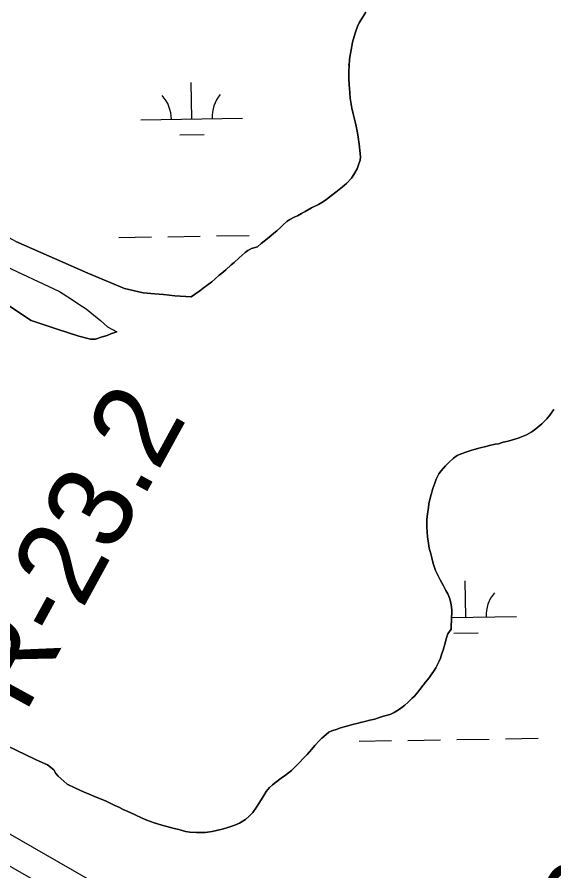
# Model space of a CAD drawing. Extents: x 3855477 to 3893699, y 299188 to 325115.
# Drawn here: x 3865378 to 3865905, y 315377 to 316217 of the extents above; entities that cross this region are included whole.
import ezdxf

# ---------------------------------------------------------------- set-up
doc = ezdxf.new("R2010")
doc.units = 0
for name, color, linetype in [('V-LEVE-TOET', 7, 'Continuous'), ('V-RIVR-EDGE', 7, 'Continuous'), ('V-RIVR-RANG-IDEN', 7, 'Continuous'), ('V-TOPO-SHOR', 7, 'Continuous'), ('V-WETL-SWMP', 7, 'Continuous')]:
    doc.layers.add(name, color=color, linetype=linetype)

msp = doc.modelspace()

# ---------------------------------------------------------------- linework, layer by layer
at = {"layer": 'V-LEVE-TOET'}
for points in [[(3865456.23, 315363.76), (3865368.76, 315414.02)], [(3865353.01, 315391.49), (3865428.99, 315348.11)]]:
    msp.add_lwpolyline(points, dxfattribs=at)
at = {"layer": 'V-RIVR-EDGE'}
msp.add_spline([(3862579.14, 316706.58), (3862618.94, 316682.57), (3862652.77, 316666.14), (3862683.04, 316656.5), (3862696.18, 316652.88), (3862701.35, 316646.89), (3862715.28, 316640.08), (3862730.01, 316634.47), (3862738.78, 316633.65), (3862748.32, 316626.05), (3862763.45, 316620.43), (3862771.01, 316614.84), (3862792.51, 316606.02), (3862806.84, 316598.81), (3862817.99, 316594.4), (3862834.31, 316586.78), (3862853.02, 316578.37), (3862861.77, 316570.77), (3862880.08, 316564.75), (3862890.05, 316564.73), (3862900.01, 316564.3), (3862907.58, 316561.49), (3862923.9, 316554.68), (3862944.6, 316544.66), (3862975.64, 316529.04), (3863008.68, 316511.03), (3863036.93, 316493.42), (3863051.26, 316484.22), (3863059.61, 316479.82), (3863073.14, 316469.42), (3863078.7, 316461.84), (3863091.04, 316455.43), (3863113.73, 316446.6), (3863137.23, 316440.57), (3863166.3, 316430.53), (3863183.42, 316425.71), (3863207.7, 316412.1), (3863228, 316399.69), (3863238.35, 316395.68), (3863252.68, 316390.47), (3863259.44, 316385.27), (3863266.6, 316378.08), (3863269.37, 316370.9), (3863279.32, 316363.3), (3863294.44, 316355.69), (3863309.17, 316346.89), (3863343, 316331.26), (3863355.34, 316322.06), (3863380.4, 316304.47), (3863423.37, 316277.26), (3863452.02, 316258.46), (3863472.72, 316247.65), (3863532.42, 316214.82), (3863576.2, 316192.79), (3863612.02, 316173.97), (3863662.97, 316147.94), (3863701.98, 316129.91), (3863762.09, 316101.46), (3863803.49, 316080.64), (3863847.67, 316056.62), (3863876.33, 316044.19), (3863896.63, 316031.79), (3863917.72, 316020.58), (3863971.85, 315991.35), (3864020.81, 315966.12), (3864054.23, 315946.51), (3864091.65, 315926.89), (3864114.73, 315913.68), (3864131.85, 315906.86), (3864146.97, 315897.66), (3864174.04, 315883.64), (3864183.18, 315874.06), (3864194.33, 315870.44), (3864207.47, 315866.82), (3864224.19, 315858.81), (3864239.32, 315850.4), (3864262.4, 315839.98), (3864273.56, 315837.17), (3864288.68, 315830.35), (3864303.82, 315827.93), (3864315.37, 315825.11), (3864338.47, 315817.08), (3864360.77, 315810.65), (3864391.41, 315792.24), (3864418.87, 315776.23), (3864435.97, 315762.24), (3864459.04, 315741.86), (3864510.37, 315709.85), (3864535.44, 315695.84), (3864548.97, 315685.44), (3864561.3, 315675.85), (3864568.85, 315666.66), (3864582.37, 315656.66), (3864595.1, 315647.07), (3864600.67, 315641.08), (3864607.02, 315633.09), (3864612.59, 315626.3), (3864620.15, 315622.69), (3864637.27, 315615.88), (3864659.57, 315609.05), (3864678.28, 315601.03), (3864697.4, 315595.4), (3864745.56, 315571.77), (3864769.85, 315563.74), (3864787.37, 315555.73), (3864811.24, 315540.52), (3864821.2, 315537.71), (3864833.16, 315537.68), (3864842.32, 315536.46), (3864849.48, 315531.26), (3864857.43, 315522.87), (3864872.16, 315516.86), (3864908, 315506.01), (3864925.13, 315500.39), (3864937.87, 315498.76), (3864948.62, 315491.56), (3864956.98, 315489.55), (3864964.15, 315487.54), (3865017.51, 315468.28), (3865068.47, 315449.82), (3865096.34, 315439.39), (3865128.59, 315424.96), (3865154.87, 315414.93), (3865175.96, 315401.73), (3865212.19, 315385.7), (3865243.63, 315368.48), (3865263.13, 315356.48), (3865277.85, 315348.07), (3865296.96, 315338.06), (3865316.47, 315331.24), (3865337.16, 315318.04), (3865369.39, 315298.43), (3865405.2, 315275.22), (3865431.87, 315259.61), (3865448.19, 315254), (3865473.66, 315238.39), (3865499.13, 315224.78), (3865515.06, 315217.96), (3865531.77, 315209.15), (3865549.68, 315199.54), (3865571.18, 315191.52), (3865609, 315173.09), (3865653.97, 315145.48), (3865693.76, 315123.07), (3865732.77, 315101.85), (3865776.94, 315077.43), (3865798.43, 315063.82), (3865826.69, 315046.62), (3865853.35, 315032.6), (3865883.2, 315017.39), (3865895.15, 315011.38), (3865904.29, 315003.78), (3865913.04, 314994.59), (3865919.8, 314990.19), (3865927.77, 314987.38), (3865939.71, 314983.37), (3865950.47, 314980.55), (3865961.62, 314976.54), (3865977.53, 314967.34), (3866028.88, 314942.9), (3866056.75, 314928.48), (3866076.64, 314915.28), (3866096.53, 314901.68), (3866120.41, 314888.47), (3866143.9, 314878.05), (3866161.41, 314867.25), (3866178.14, 314862.82), (3866201.24, 314856.79), (3866223.14, 314850.36), (3866245.83, 314837.55), (3866263.73, 314827.14), (3866282.84, 314818.72), (3866292.41, 314818.7), (3866300.78, 314818.28), (3866309.94, 314816.27), (3866326.66, 314808.65), (3866348.53, 314791.06), (3866360.08, 314786.25), (3866377.59, 314778.64), (3866387.55, 314775.02), (3866394.31, 314767.44), (3866401.87, 314762.24), (3866413.81, 314757.03), (3866423.36, 314751.42), (3866432.12, 314749.81), (3866437.69, 314746.21), (3866445.65, 314739.41), (3866454.4, 314732.22), (3866485.45, 314718.99), (3866510.53, 314708.56), (3866533.21, 314691.37), (3866541.97, 314691.35), (3866549.94, 314690.93), (3866556.31, 314686.53), (3866561.87, 314678.55), (3866573.8, 314670.15), (3866598.9, 314663.71), (3866631.14, 314649.28), (3866660.61, 314640.44), (3866694.86, 314628.4), (3866748.2, 314604.36), (3866780.45, 314591.52), (3866811.1, 314575.51), (3866846.93, 314561.47), (3866895.5, 314539.03), (3866932.13, 314524.59), (3866954.81, 314513.38), (3866988.26, 314500.54), (3867018.51, 314486.52), (3867041.2, 314475.3), (3867068.66, 314458.5), (3867097.31, 314440.09), (3867123.99, 314432.46), (3867147.11, 314433.2), (3867169.41, 314427.96), (3867197.28, 314417.13), (3867215.2, 314410.71), (3867238.69, 314401.49), (3867251.43, 314396.27), (3867258.61, 314395.86), (3867271.36, 314397.42), (3867288.1, 314397.78), (3867302.45, 314396.15), (3867345.46, 314385.28), (3867427.5, 314359.57), (3867438.25, 314357.95), (3867445.03, 314357.93), (3867453.42, 314369.47), (3867458.24, 314381.41), (3867462.26, 314395.75), (3867462.28, 314404.12), (3867460.7, 314411.7), (3867457.12, 314414.1), (3867450.75, 314416.11), (3867442.78, 314416.52), (3867438.8, 314420.12), (3867443.19, 314422.1), (3867451.58, 314428.06), (3867458.77, 314437.21), (3867459.58, 314442.79), (3867460, 314450.75), (3867463.6, 314455.13), (3867470.8, 314463.88), (3867472, 314469.46), (3867472.42, 314477.03), (3867471.64, 314485), (3867465.71, 314504.54), (3867463.75, 314514.51), (3867463.37, 314524.48), (3867464.21, 314541.21), (3867469.07, 314571.09), (3867474.67, 314579.84), (3867478.26, 314581.43), (3867485.04, 314582.61), (3867525.27, 314574.94), (3867536.02, 314568.93), (3867545.17, 314565.72), (3867555.14, 314566.49), (3867569.88, 314566.06), (3867581.03, 314559.65), (3867584.99, 314552.07), (3867591.75, 314543.69), (3867611.65, 314532.88), (3867627.95, 314518.09), (3867650.21, 314493.33), (3867659.75, 314484.93), (3867663.31, 314472.97), (3867663.27, 314455.43), (3867660.06, 314447.47), (3867647.3, 314446.31), (3867632.15, 314444.75), (3867612.61, 314438.42), (3867582.29, 314425.34)], degree=3, dxfattribs=at)
at = {"layer": 'V-TOPO-SHOR'}
for points in [[(3865548.8, 315941.55), (3865552.11, 315943.8), (3865557.29, 315947.61), (3865560.75, 315950), (3865564.06, 315952.54), (3865569.1, 315956.35), (3865572.13, 315959.03), (3865576.31, 315962.7), (3865579.05, 315964.82), (3865582.8, 315968.21), (3865588.28, 315972.87), (3865591.17, 315975.41), (3865595.93, 315979.94), (3865601.84, 315985.16), (3865604.58, 315987.28), (3865608.17, 315988.96), (3865614.05, 315990.61), (3865617.8, 315993.86), (3865620.68, 315996.4), (3865623.7, 315998.51), (3865627.6, 316001.9), (3865630.2, 316004.31), (3865633.08, 316006.42), (3865636.83, 316009.95), (3865639.42, 316012.22), (3865643.03, 316015.61), (3865645.77, 316017.58), (3865650.22, 316019.82), (3865653.24, 316021.36), (3865657.26, 316023.61), (3865661, 316025.43), (3865667.04, 316028.94), (3865674.08, 316032.44), (3865677.24, 316034.41), (3865680.84, 316036.66), (3865686.89, 316041.17), (3865691.21, 316044.41), (3865697.7, 316049.77), (3865701.59, 316053.16), (3865706.36, 316058.4), (3865708.68, 316061.81), (3865711.88, 316067.49), (3865713.5, 316071.34), (3865714.83, 316075.89), (3865715.29, 316079.32), (3865714.79, 316085.61), (3865713.99, 316091.77), (3865713.06, 316098.64), (3865712.25, 316102.79), (3865710.89, 316109.38), (3865710.21, 316113.53), (3865708.57, 316120.26), (3865706.92, 316127), (3865705.31, 316136.88), (3865704.79, 316142.17), (3865704.02, 316150.47), (3865703.94, 316155.9), (3865703.87, 316163.62), (3865704.07, 316168.62), (3865704.56, 316175.33), (3865705.48, 316180.89), (3865706.84, 316188.03), (3865707.6, 316192.02), (3865709.08, 316197.72), (3865710.27, 316201.71), (3865712.47, 316207.4), (3865713.94, 316211.1), (3865717.14, 316216.36), (3865720.62, 316221.47)], [(3865376.37, 315995.98), (3865447.26, 315964.8), (3865483.19, 315949.78), (3865501.75, 315945.64), (3865513.01, 315944.58), (3865521.65, 315943.74), (3865532.91, 315942.68), (3865548.8, 315941.55)], [(3865361.87, 315973.59), (3865419.47, 315946.87), (3865431.05, 315939.24), (3865438.52, 315934.46), (3865445.6, 315929.69), (3865452.87, 315923.79), (3865459.58, 315918.27), (3865466.47, 315912.19), (3865475.84, 315907.14)], [(3865341.27, 315951.51), (3865391.66, 315918.3), (3865406.27, 315913.45), (3865416.19, 315909.96), (3865427.25, 315906.47), (3865438.48, 315902.78), (3865449.73, 315899.85), (3865454.61, 315899.79)], [(3865454.61, 315899.79), (3865460.35, 315901.73), (3865466.08, 315903.67), (3865469.96, 315905.06), (3865475.84, 315907.14)], [(3865905.53, 315830.82), (3865901.32, 315825), (3865898.43, 315821.6), (3865893.52, 315816.65), (3865887.75, 315811.71), (3865883.86, 315808.89), (3865878.68, 315805.8), (3865875.1, 315804.41), (3865870.36, 315802.6), (3865863.77, 315800.66), (3865860.47, 315799.7), (3865855.46, 315798.46), (3865850.87, 315797.08), (3865847.57, 315796.54), (3865842.28, 315795.46), (3865838.55, 315794.49), (3865832.96, 315793.12), (3865829.23, 315792.02)], [(3865829.23, 315792.02), (3865823.93, 315790.5), (3865819.92, 315789.25), (3865814.18, 315787.17), (3865810.45, 315785.49), (3865806.84, 315782.81), (3865801.79, 315778.29), (3865798.76, 315775.18), (3865794.71, 315770.51), (3865792.39, 315767.39), (3865789.62, 315762.27), (3865788.3, 315758.42), (3865786.52, 315752.87), (3865784.75, 315747.17), (3865783.71, 315743.61), (3865782.51, 315738.04), (3865782.05, 315734.33), (3865781.27, 315727.77), (3865780.64, 315722.92), (3865780.42, 315715.34), (3865780.8, 315710.19), (3865781.32, 315705.33), (3865782.25, 315699.03), (3865782.92, 315694.31), (3865784.43, 315688.72), (3865785.54, 315684.71), (3865786.91, 315679.4), (3865787.74, 315676.25), (3865789.12, 315672.23), (3865791.92, 315666.49), (3865793.74, 315663.04), (3865796.97, 315657.15), (3865799.35, 315652.55), (3865801.18, 315649.39), (3865802.99, 315644.65), (3865804.09, 315640.35), (3865804.9, 315636.48), (3865805.15, 315632.91), (3865805.12, 315629.91), (3865804.95, 315626.77), (3865804.39, 315614.62)], [(3865804.39, 315614.62), (3865801.2, 315609.94), (3865799.87, 315606.24), (3865798.38, 315599.97), (3865796.61, 315593.98), (3865795.43, 315590.71), (3865793.81, 315586.15), (3865792.63, 315583.16), (3865790.74, 315579.32), (3865789.28, 315576.48), (3865787.68, 315573.92), (3865784.78, 315569.66), (3865782.89, 315566.82), (3865779.27, 315562.43), (3865776.96, 315559.74), (3865773.62, 315555.34), (3865771.6, 315552.79), (3865768.41, 315548.82), (3865765.81, 315546.42), (3865761.92, 315542.6), (3865759.03, 315539.92), (3865753.7, 315535.83), (3865748.52, 315532.59), (3865745.22, 315531.05), (3865741.78, 315529.95), (3865738.05, 315528.98), (3865732.89, 315527.32), (3865729.3, 315526.22), (3865724.43, 315525.12), (3865719.56, 315523.89), (3865716.55, 315523.2), (3865711.82, 315521.82), (3865708.81, 315521.14), (3865704.08, 315519.9), (3865700.64, 315518.94), (3865695.77, 315517.7), (3865692.33, 315516.45), (3865687.17, 315514.79), (3865684.29, 315513.25), (3865681.41, 315510.99), (3865677.23, 315507.32), (3865674.63, 315504.77), (3865670.44, 315500.1), (3865667.54, 315496.7), (3865662.77, 315491.46), (3865659.74, 315488.06), (3865655.11, 315483.11), (3865650.64, 315478.86), (3865647.32, 315475.76), (3865641.41, 315471.1), (3865637.38, 315468), (3865631.76, 315463.77), (3865628.88, 315461.51), (3865625.71, 315458.83), (3865622.67, 315455), (3865620.34, 315451.02), (3865615.98, 315444.06), (3865613.07, 315439.52), (3865609.3, 315434.41), (3865605.55, 315430.31), (3865602.23, 315427.34), (3865596.19, 315423.83), (3865591.6, 315421.88), (3865585, 315419.52), (3865580.55, 315418.13), (3865573.82, 315416.63), (3865569.52, 315415.53), (3865562.51, 315414.75), (3865558.08, 315414.51), (3865553.93, 315414.55), (3865547.5, 315415.04), (3865543.23, 315415.8), (3865536.67, 315417.58), (3865532.25, 315418.49), (3865524.98, 315420.42), (3865519.99, 315421.9), (3865512.58, 315424.12), (3865505.32, 315426.91), (3865500.63, 315428.82), (3865493.66, 315432.04), (3865488.96, 315434.23), (3865481.99, 315437.44), (3865477.73, 315439.63), (3865473.89, 315441.39), (3865468.62, 315443.87), (3865465.21, 315445.34), (3865459.66, 315447.68), (3865455.54, 315449.58), (3865448.42, 315452.37), (3865442.87, 315454.71), (3865435.19, 315458.36), (3865426.8, 315462.17), (3865423.54, 315465.06), (3865418.01, 315469.98), (3865415.76, 315472.86), (3865413.94, 315476.16), (3865407.56, 315481.38), (3865402.43, 315483.57), (3865395.89, 315486.35), (3865385.51, 315491.32), (3865378.11, 315495.11)], [(3865378.11, 315495.11), (3865367.16, 315500.37)]]:
    msp.add_lwpolyline(points, dxfattribs=at)
at = {"layer": 'V-WETL-SWMP'}
for p, q in [((3865703.06, 316169.77), (3865704.15, 316169.79)), ((3865549.31, 316116.52), (3865548.73, 316152.51)), ((3865499.32, 316115.7), (3865599.31, 316117.33)), ((3865537.56, 316100.89), (3865561.56, 316101.29)), ((3865477.79, 315999.91), (3865509.79, 316000.43)), ((3865525.79, 316000.69), (3865557.78, 316001.21)), ((3865573.78, 316001.47), (3865605.78, 316001.99)), ((3865818.77, 315626.33), (3865818.18, 315662.32)), ((3865804.92, 315626.1), (3865868.76, 315627.14)), ((3865807.02, 315610.7), (3865831.02, 315611.09)), ((3865713.89, 315504.53), (3865745.89, 315505.05)), ((3865761.89, 315505.31), (3865793.88, 315505.83)), ((3865809.88, 315506.09), (3865841.88, 315506.62)), ((3865857.87, 315506.88), (3865889.87, 315507.4))]:
    msp.add_line(p, q, dxfattribs=at)
for points in [[(3865548.8, 315941.55), (3865532.91, 315942.68), (3865521.65, 315943.74), (3865513.01, 315944.58), (3865501.75, 315945.64), (3865483.19, 315949.78), (3865447.26, 315964.8), (3865376.37, 315995.98), (3865308.75, 316033.1), (3865202.29, 316083.1), (3865135.21, 316123.01), (3865132.06, 316125.98), (3865130.58, 316130.57), (3865130.46, 316131.34), (3865131.25, 316133.88), (3865132.56, 316137.56), (3865135.01, 316140.84), (3865138.11, 316144.63), (3865142.62, 316149.42), (3865156.58, 316158.07), (3865196, 316176.51), (3865249.62, 316198.18), (3865283.95, 316210.81), (3865338.75, 316221.36)], [(3865720.62, 316221.47), (3865717.14, 316216.36), (3865713.94, 316211.1), (3865712.47, 316207.4), (3865710.27, 316201.71), (3865709.08, 316197.72), (3865707.6, 316192.02), (3865706.84, 316188.03), (3865705.48, 316180.89), (3865704.56, 316175.33), (3865704.07, 316168.62), (3865703.87, 316163.62), (3865703.94, 316155.9), (3865704.02, 316150.47), (3865704.79, 316142.17), (3865705.31, 316136.88), (3865706.92, 316127), (3865708.57, 316120.26), (3865710.21, 316113.53), (3865710.89, 316109.38), (3865712.25, 316102.79), (3865713.06, 316098.64), (3865713.99, 316091.77), (3865714.79, 316085.61), (3865715.29, 316079.32), (3865714.83, 316075.89), (3865713.5, 316071.33), (3865711.88, 316067.49), (3865708.68, 316061.81), (3865706.36, 316058.4), (3865701.59, 316053.16), (3865697.7, 316049.77), (3865691.21, 316044.41), (3865686.89, 316041.17), (3865680.84, 316036.66)], [(3865680.84, 316036.66), (3865677.24, 316034.41), (3865674.08, 316032.44), (3865667.04, 316028.94), (3865661, 316025.43), (3865657.26, 316023.61), (3865653.24, 316021.36), (3865650.22, 316019.82), (3865645.77, 316017.58), (3865643.03, 316015.61), (3865639.42, 316012.22), (3865636.83, 316009.96), (3865633.08, 316006.42), (3865630.2, 316004.31), (3865627.6, 316001.9), (3865623.7, 315998.51), (3865620.68, 315996.4), (3865617.8, 315993.86), (3865614.05, 315990.61), (3865608.17, 315988.96), (3865604.58, 315987.28), (3865601.84, 315985.16), (3865595.93, 315979.94), (3865591.17, 315975.41), (3865588.28, 315972.87), (3865582.8, 315968.21), (3865579.05, 315964.82), (3865576.31, 315962.7), (3865572.13, 315959.03), (3865569.1, 315956.35), (3865564.06, 315952.54), (3865560.75, 315950), (3865557.29, 315947.61), (3865552.11, 315943.8), (3865548.8, 315941.55)], [(3865361.87, 315973.59), (3865419.48, 315946.87), (3865431.05, 315939.24), (3865438.51, 315934.46), (3865445.6, 315929.69), (3865452.87, 315923.79), (3865459.58, 315918.27), (3865466.47, 315912.19), (3865475.84, 315907.14), (3865469.96, 315905.06), (3865466.08, 315903.67), (3865460.35, 315901.73), (3865454.61, 315899.79), (3865449.73, 315899.85), (3865438.48, 315902.78), (3865427.24, 315906.47), (3865416.19, 315909.96), (3865406.27, 315913.45), (3865391.66, 315918.3), (3865341.27, 315951.51)], [(3865695.77, 315517.7), (3865700.65, 315518.94), (3865704.08, 315519.9), (3865708.81, 315521.14), (3865711.82, 315521.82), (3865716.55, 315523.2), (3865719.56, 315523.89), (3865724.43, 315525.12), (3865729.3, 315526.22), (3865732.89, 315527.32), (3865738.05, 315528.98), (3865741.78, 315529.95), (3865745.22, 315531.05), (3865748.52, 315532.59), (3865753.7, 315535.83), (3865759.03, 315539.91), (3865761.92, 315542.6), (3865765.81, 315546.42), (3865768.41, 315548.82), (3865771.6, 315552.79), (3865773.62, 315555.34), (3865776.96, 315559.74), (3865779.27, 315562.43), (3865782.89, 315566.82), (3865784.78, 315569.66), (3865787.68, 315573.92), (3865789.28, 315576.48), (3865790.74, 315579.32), (3865792.63, 315583.16), (3865793.81, 315586.15), (3865795.43, 315590.71), (3865796.6, 315593.98), (3865798.38, 315599.96), (3865799.88, 315606.24), (3865801.2, 315609.94), (3865804.39, 315614.62), (3865804.95, 315626.77), (3865805.12, 315629.91), (3865805.15, 315632.91), (3865804.9, 315636.48), (3865804.09, 315640.35), (3865802.99, 315644.65), (3865801.18, 315649.39), (3865799.35, 315652.55), (3865796.97, 315657.15), (3865793.75, 315663.04), (3865791.92, 315666.49), (3865789.12, 315672.23), (3865787.74, 315676.25), (3865786.91, 315679.4), (3865785.54, 315684.71), (3865784.43, 315688.72), (3865782.92, 315694.31), (3865782.25, 315699.03), (3865781.32, 315705.33), (3865780.8, 315710.19), (3865780.42, 315715.34), (3865780.64, 315722.92), (3865781.27, 315727.77), (3865782.05, 315734.34), (3865782.51, 315738.05), (3865783.71, 315743.61), (3865784.75, 315747.17), (3865786.53, 315752.87), (3865788.3, 315758.42), (3865789.62, 315762.27), (3865792.39, 315767.39), (3865794.71, 315770.51), (3865798.76, 315775.18), (3865801.79, 315778.29), (3865806.84, 315782.82), (3865810.45, 315785.49), (3865814.18, 315787.17), (3865819.92, 315789.25), (3865823.93, 315790.5), (3865829.23, 315792.02), (3865832.96, 315793.12), (3865838.55, 315794.49), (3865842.28, 315795.45), (3865847.58, 315796.54), (3865850.87, 315797.08), (3865855.46, 315798.46), (3865860.47, 315799.7), (3865863.77, 315800.66), (3865870.36, 315802.6), (3865875.1, 315804.41), (3865878.68, 315805.8), (3865883.86, 315808.89), (3865887.75, 315811.71), (3865893.52, 315816.65), (3865898.43, 315821.6), (3865901.32, 315825), (3865905.53, 315830.82)], [(3865367.16, 315500.37), (3865378.11, 315495.11), (3865385.51, 315491.32), (3865395.89, 315486.35), (3865402.43, 315483.57), (3865407.56, 315481.38), (3865413.93, 315476.16), (3865415.76, 315472.86), (3865418.02, 315469.98), (3865423.54, 315465.06), (3865426.8, 315462.17), (3865435.19, 315458.36), (3865442.87, 315454.71), (3865448.42, 315452.37), (3865455.54, 315449.58), (3865459.66, 315447.68), (3865465.21, 315445.34), (3865468.62, 315443.87), (3865473.89, 315441.39), (3865477.73, 315439.63), (3865481.99, 315437.44), (3865488.96, 315434.23), (3865493.66, 315432.04), (3865500.63, 315428.82), (3865505.32, 315426.91), (3865512.58, 315424.12), (3865519.99, 315421.9), (3865524.98, 315420.42), (3865532.25, 315418.49), (3865536.67, 315417.59), (3865543.23, 315415.8), (3865547.5, 315415.04), (3865553.93, 315414.55), (3865558.08, 315414.51), (3865562.51, 315414.75), (3865569.52, 315415.53), (3865573.82, 315416.63), (3865580.55, 315418.13), (3865585, 315419.52), (3865591.6, 315421.88), (3865596.19, 315423.83), (3865602.23, 315427.34), (3865605.54, 315430.31), (3865609.3, 315434.41), (3865613.07, 315439.52), (3865615.98, 315444.06), (3865620.34, 315451.02), (3865622.67, 315455), (3865625.71, 315458.83), (3865628.88, 315461.51), (3865631.76, 315463.77), (3865637.38, 315468), (3865641.41, 315471.1), (3865647.32, 315475.76), (3865650.64, 315478.86), (3865655.11, 315483.11), (3865659.74, 315488.06), (3865662.77, 315491.46), (3865667.54, 315496.7), (3865670.44, 315500.1), (3865674.63, 315504.77), (3865677.23, 315507.32), (3865681.41, 315510.99), (3865684.29, 315513.25), (3865687.17, 315514.79), (3865692.33, 315516.45), (3865695.77, 315517.7)]]:
    msp.add_lwpolyline(points, dxfattribs=at)
for centre, start, end in [((3865494.07, 316116.09), 0.16154, 41.7052), ((3865604.54, 316117.89), 140.16154, 181.7052), ((3865873.99, 315627.7), 140.16154, 181.70519)]:
    msp.add_arc(centre, 35.25, start, end, dxfattribs=at)

# ---------------------------------------------------------------- texts
at = {"layer": 'V-RIVR-RANG-IDEN'}
for s, rotation, p in [('R-23.2', 61.29541, (3865385.33, 315530.54)), ('D-040', 61.62633, (3865904.21, 315201.12))]:
    msp.add_text(s, height=83, rotation=rotation, dxfattribs=at).set_placement(p)

doc.saveas('drawing.dxf')
